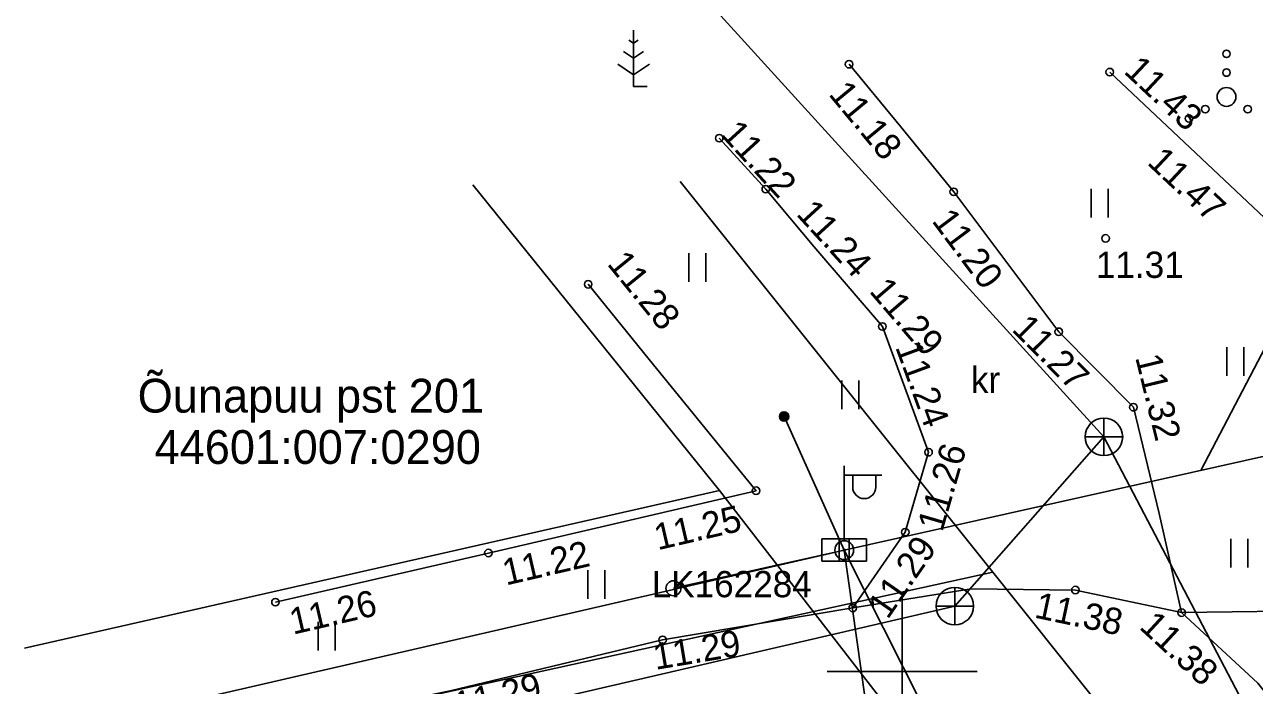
# Model space of a CAD drawing. Extents: x 554198 to 554371, y 6593448 to 6593563.
# Drawn here: x 554226.6 to 554259.39, y 6593499.63 to 6593517.24 of the extents above; entities that cross this region are included whole.
import ezdxf

# ---------------------------------------------------------------- set-up
doc = ezdxf.new("R2010")
doc.units = 0
for name, color, linetype in [('AED', 7, 'Continuous'), ('ELRAJATISMP', 7, 'Continuous'), ('HALJASTUS', 7, 'Continuous'), ('KKAEV', 7, 'Continuous'), ('KORGUS-EH2000', 7, 'Continuous'), ('KTRASS', 7, 'Continuous'), ('MPOHULIIN', 7, 'Continuous'), ('PIIR', 7, 'Continuous'), ('POST', 7, 'Continuous'), ('PUU', 7, 'Continuous'), ('TEE', 7, 'Continuous'), ('VORK', 7, 'Continuous'), ('VTRASS', 7, 'Continuous')]:
    doc.layers.add(name, color=color, linetype=linetype)

msp = doc.modelspace()

# ---------------------------------------------------------------- linework, layer by layer
at = {"layer": 'AED'}
msp.add_lwpolyline([(554241.625, 6593510.316), (554243.249, 6593508.316), (554246.101, 6593504.814), (554238.966, 6593503.155), (554233.289, 6593501.845)], dxfattribs=at)
at = {"layer": 'ELRAJATISMP'}
for p, q in [((554249.049, 6593503.529), (554247.855, 6593503.529)), ((554247.855, 6593503.529), (554247.855, 6593502.933)), ((554248.316, 6593503.529), (554248.316, 6593502.933)), ((554248.588, 6593503.529), (554248.588, 6593502.933)), ((554249.049, 6593502.933), (554249.049, 6593503.529)), ((554247.855, 6593502.933), (554249.049, 6593502.933))]:
    msp.add_line(p, q, dxfattribs=at)
at = {"layer": 'HALJASTUS'}
for p, q in [((554255.033, 6593512.861), (554255.033, 6593512.1)), ((554255.488, 6593512.861), (554255.488, 6593512.1)), ((554244.308, 6593511.142), (554244.308, 6593510.381)), ((554244.763, 6593511.142), (554244.763, 6593510.381)), ((554258.649, 6593508.638), (554258.649, 6593507.877)), ((554259.104, 6593508.638), (554259.104, 6593507.877)), ((554248.387, 6593507.75), (554248.387, 6593506.989)), ((554248.842, 6593507.75), (554248.842, 6593506.989)), ((554258.755, 6593503.533), (554258.755, 6593502.772)), ((554259.21, 6593503.533), (554259.21, 6593502.772)), ((554241.616, 6593502.694), (554241.616, 6593501.933)), ((554242.071, 6593502.694), (554242.071, 6593501.933)), ((554234.427, 6593501.321), (554234.427, 6593500.56)), ((554234.882, 6593501.321), (554234.882, 6593500.56))]:
    msp.add_line(p, q, dxfattribs=at)
msp.add_lwpolyline([(554271.046, 6593507.591), (554269.64, 6593507.3), (554268, 6593507.31), (554264.79, 6593510.51), (554259.66, 6593512.09), (554255.53, 6593515.97)], dxfattribs=at)
for centre, radius in [((554258.643, 6593516.458), 0.1), ((554258.643, 6593515.958), 0.1), ((554258.643, 6593515.308), 0.25), ((554258.078, 6593514.983), 0.1), ((554259.208, 6593514.983), 0.1), ((554257.643, 6593514.733), 0.1)]:
    msp.add_circle(centre, radius, dxfattribs=at)
at = {"layer": 'KKAEV'}
for p, q in [((554255.375, 6593505.75), (554255.375, 6593506.75)), ((554254.875, 6593506.25), (554255.875, 6593506.25)), ((554251.4, 6593501.24), (554251.4, 6593502.24)), ((554250.9, 6593501.74), (554251.9, 6593501.74))]:
    msp.add_line(p, q, dxfattribs=at)
for centre in [(554255.375, 6593506.25), (554251.4, 6593501.74)]:
    msp.add_circle(centre, 0.5, dxfattribs=at)
at = {"layer": 'KORGUS-EH2000'}
for centre in [(554248.58, 6593516.18), (554255.53, 6593515.97), (554245.12, 6593514.21), (554246.36, 6593512.85), (554251.37, 6593512.78), (554255.42, 6593511.54), (554241.625, 6593510.316), (554249.47, 6593509.19), (554254.17, 6593509.05), (554256.16, 6593507.04), (554250.7, 6593505.84), (554246.101, 6593504.814), (554250.08, 6593503.71), (554238.966, 6593503.155), (554254.616, 6593502.167), (554233.289, 6593501.845), (554248.68, 6593501.69), (554257.446, 6593501.567), (554243.61, 6593500.842)]:
    msp.add_circle(centre, 0.1, dxfattribs=at)
at = {"layer": 'KTRASS'}
for points in [[(554243.824, 6593518.956), (554255.375, 6593506.25)], [(554251.4, 6593501.74), (554255.375, 6593506.25)], [(554255.375, 6593506.25), (554262.98, 6593491.74)], [(554228.21, 6593496.367), (554251.4, 6593501.74)]]:
    msp.add_lwpolyline(points, dxfattribs=at)
at = {"layer": 'MPOHULIIN'}
for points in [[(554282.548, 6593510.856), (554248.452, 6593503.231)], [(554257.956, 6593505.356), (554259.983, 6593509.225), (554264.482, 6593509.225)], [(554226.975, 6593498.284), (554248.452, 6593503.231)], [(554248.452, 6593503.231), (554251.34, 6593482.787)], [(554248.452, 6593503.231), (554261.544, 6593477.284)]]:
    msp.add_lwpolyline(points, dxfattribs=at)
at = {"layer": 'PIIR'}
for p, q in [((554238.55, 6593512.967), (554245.13, 6593504.82)), ((554245.13, 6593504.82), (554226.601, 6593500.62)), ((554245.13, 6593504.82), (554255.79, 6593491.05))]:
    msp.add_line(p, q, dxfattribs=at)
at = {"layer": 'POST'}
for p, q in [((554248.452, 6593503.231), (554246.849, 6593506.792)), ((554248.452, 6593503.481), (554248.452, 6593505.481)), ((554248.452, 6593505.231), (554249.452, 6593505.231)), ((554248.679, 6593504.91), (554248.679, 6593505.231)), ((554249.291, 6593504.91), (554249.291, 6593505.231)), ((554243.899, 6593502.214), (554248.452, 6593503.231))]:
    msp.add_line(p, q, dxfattribs=at)
for centre, radius in [((554246.849, 6593506.792), 0.125), ((554246.849, 6593506.792), 0.117), ((554246.849, 6593506.792), 0.109), ((554246.849, 6593506.792), 0.102), ((554246.849, 6593506.792), 0.0938), ((554246.849, 6593506.792), 0.086), ((554246.849, 6593506.792), 0.0782), ((554246.849, 6593506.792), 0.0704), ((554246.849, 6593506.792), 0.0626), ((554246.849, 6593506.792), 0.0548), ((554246.849, 6593506.792), 0.047), ((554246.849, 6593506.792), 0.0392), ((554246.849, 6593506.792), 0.0314), ((554246.849, 6593506.792), 0.0236), ((554246.849, 6593506.792), 0.0158), ((554246.849, 6593506.792), 0.00798), ((554246.849, 6593506.792), 0.000186), ((554248.452, 6593503.231), 0.25), ((554248.452, 6593503.231), 0.0234), ((554243.899, 6593502.214), 0.2)]:
    msp.add_circle(centre, radius, dxfattribs=at)
msp.add_arc((554248.985, 6593504.91), 0.306, 180, 0, dxfattribs=at)
at = {"layer": 'PUU'}
for p, q in [((554242.837, 6593517.09), (554242.837, 6593515.59)), ((554242.837, 6593516.74), (554242.713, 6593516.823)), ((554242.961, 6593516.823), (554242.837, 6593516.74)), ((554242.837, 6593516.34), (554242.57, 6593516.518)), ((554243.104, 6593516.518), (554242.837, 6593516.34)), ((554242.413, 6593516.179), (554242.837, 6593515.897)), ((554242.837, 6593515.897), (554243.261, 6593516.179)), ((554243.197, 6593515.59), (554242.837, 6593515.59))]:
    msp.add_line(p, q, dxfattribs=at)
at = {"layer": 'TEE'}
for points in [[(554248.58, 6593516.18), (554249.96, 6593514.51), (554251.37, 6593512.78), (554254.17, 6593509.05), (554256.16, 6593507.04), (554256.85, 6593504.21), (554257.446, 6593501.567)], [(554248.68, 6593501.69), (554250.08, 6593503.71), (554250.7, 6593505.84), (554249.47, 6593509.19), (554247.64, 6593511.32), (554246.36, 6593512.85), (554245.12, 6593514.21)], [(554272.497, 6593502.867), (554270.945, 6593502.819), (554269.137, 6593502.567), (554267.385, 6593502.182), (554264.175, 6593501.658), (554257.446, 6593501.567)], [(554265.95, 6593476.82), (554265.59, 6593480.97), (554265.19, 6593483.27), (554264.491, 6593488.567), (554263.957, 6593491.18), (554262.564, 6593494.685), (554261.213, 6593497.518), (554259.482, 6593499.687), (554257.446, 6593501.567), (554254.616, 6593502.167), (554251.838, 6593502.198), (554248.68, 6593501.69), (554243.61, 6593500.842), (554237.947, 6593499.485), (554232.294, 6593498.32)]]:
    msp.add_lwpolyline(points, dxfattribs=at)
at = {"layer": 'VORK'}
for p, q in [((554250, 6593502), (554250, 6593498)), ((554248, 6593500), (554252, 6593500))]:
    msp.add_line(p, q, dxfattribs=at)
at = {"layer": 'VTRASS'}
for points in [[(554260.701, 6593492.276), (554252.41, 6593502.64), (554244.08, 6593513.051)], [(554228.019, 6593497.285), (554252.41, 6593502.64)]]:
    msp.add_lwpolyline(points, dxfattribs=at)

# ---------------------------------------------------------------- texts
at = {"layer": 'ELRAJATISMP'}
msp.add_text('LK162284', height=0.7, dxfattribs=at).set_placement((554243.319, 6593501.976))
at = {"layer": 'KORGUS-EH2000'}
for s, rotation, p in [(' 11.43 ', 316.7877, (554255.69, 6593516.14)), (' 11.18 ', 309.5685, (554247.848, 6593515.575)), (' 11.22 ', 312.3575, (554244.962, 6593514.487)), (' 11.47 ', 316.7877, (554256.31, 6593513.712)), (' 11.24 ', 312.3575, (554246.974, 6593512.366)), (' 11.20 ', 306.8945, (554250.61, 6593512.21)), (' 11.28 ', 309.0766, (554241.946, 6593511.055)), (' 11.29 ', 310.6677, (554248.927, 6593510.319)), (' 11.27 ', 314.7135, (554252.712, 6593509.275)), (' 11.24 ', 290.1614, (554249.716, 6593508.888)), (' 11.32 ', 283.7023, (554256.145, 6593508.624)), (' 11.26 ', 73.7708, (554250.992, 6593503.444)), (' 11.25 ', 13.0896, (554243.226, 6593503.167)), (' 11.22 ', 12.9939, (554239.18, 6593502.229)), (' 11.29 ', 55.2754, (554249.461, 6593501.149)), (' 11.26 ', 12.9939, (554233.503, 6593500.919)), (' 11.38 ', 348.0297, (554253.241, 6593501.493)), (' 11.38 ', 317.2813, (554256.098, 6593501.335)), (' 11.29 ', 9.4953, (554243.164, 6593499.996)), (' 11.29 ', 13.4755, (554237.897, 6593498.686))]:
    msp.add_text(s, height=0.7, rotation=rotation, dxfattribs=at).set_placement(p)
msp.add_text(' 11.31 ', height=0.7, dxfattribs=at).set_placement((554254.9, 6593510.486))
at = {"layer": 'PIIR'}
for s, p in [('Õunapuu pst 201', (554229.616, 6593506.897)), ('44601:007:0290', (554230.066, 6593505.529))]:
    msp.add_text(s, height=0.9, dxfattribs=at).set_placement(p)
at = {"layer": 'TEE'}
msp.add_text('kr', height=0.7, dxfattribs=at).set_placement((554251.828, 6593507.421))

doc.saveas('drawing.dxf')
